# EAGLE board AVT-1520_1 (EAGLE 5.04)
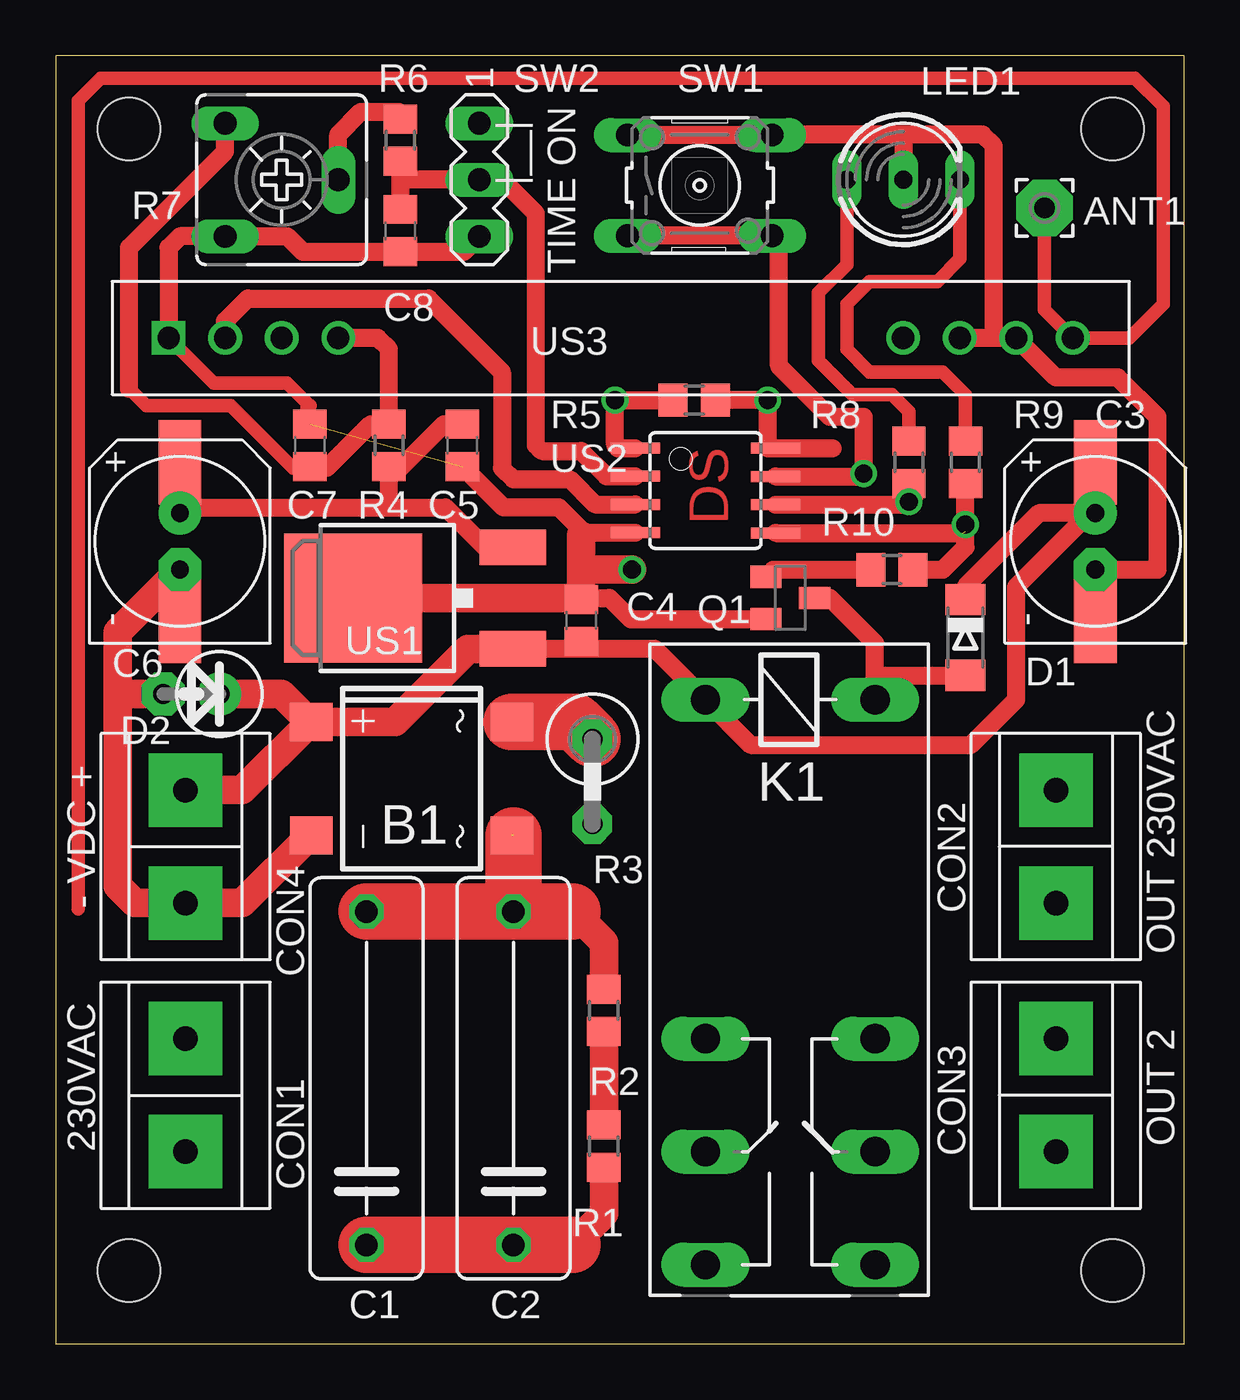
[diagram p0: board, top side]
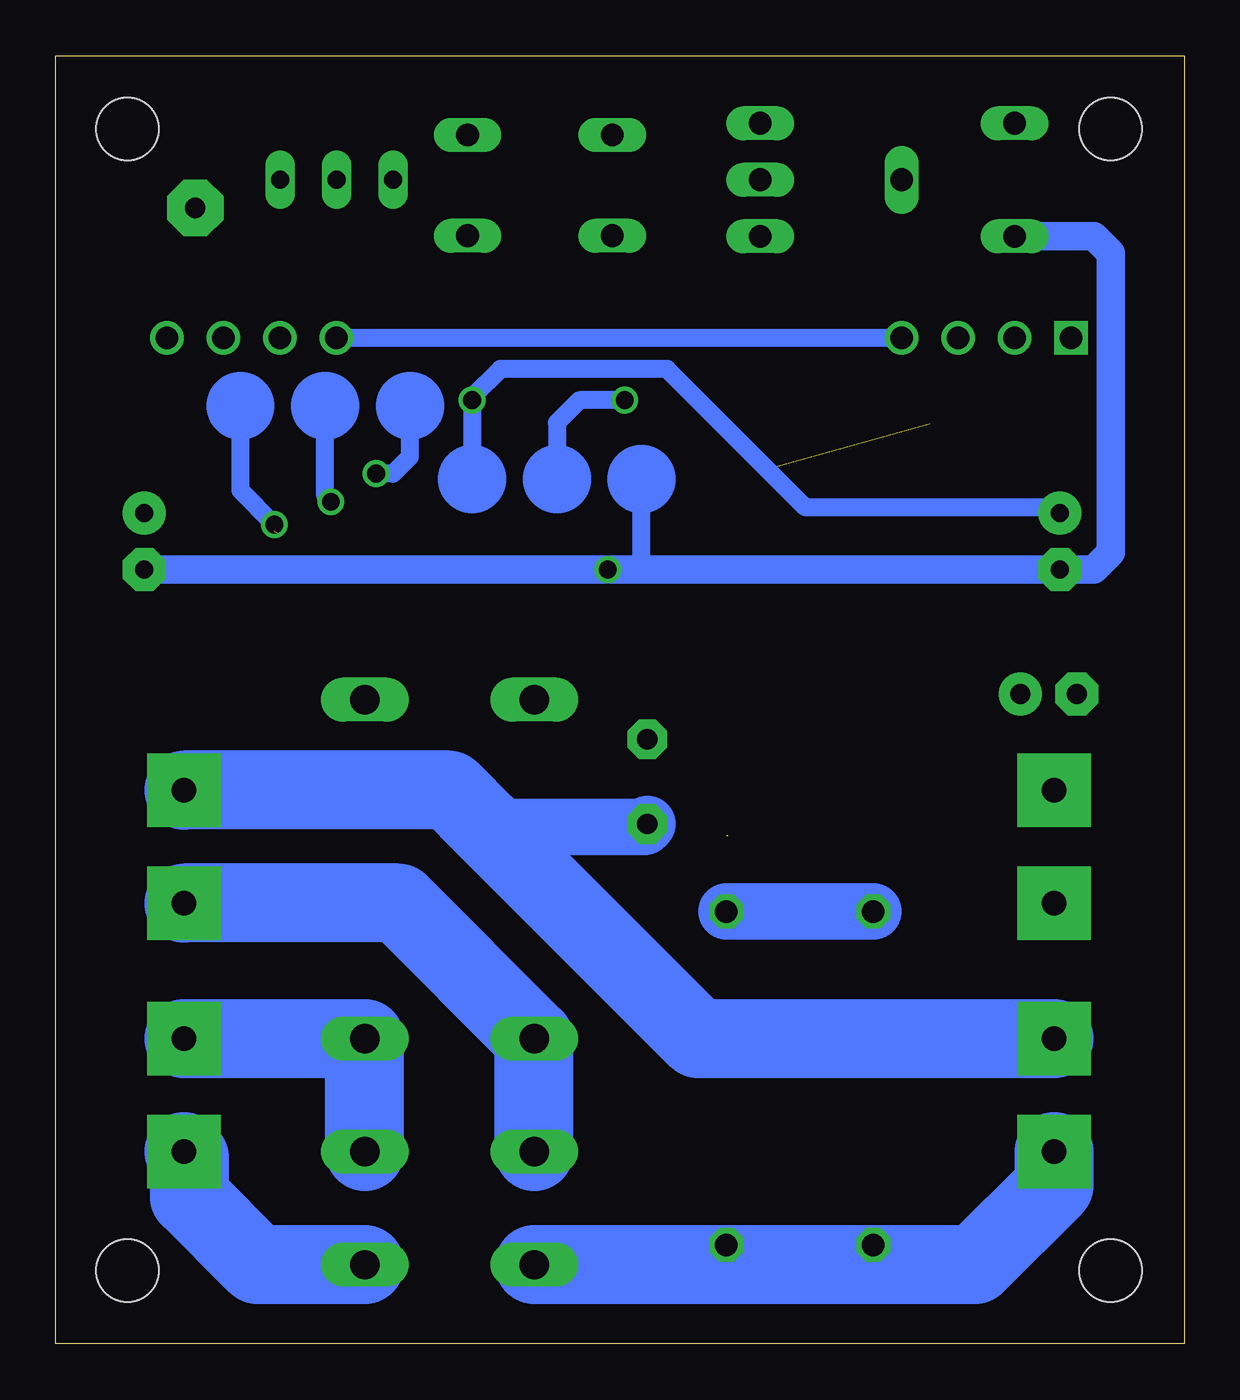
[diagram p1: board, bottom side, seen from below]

Size 50.72 x 57.9 mm. Coordinates in mm from the lower left corner, seen from the top.
Outline: 0,0 50.72,0 50.72,57.9 0,57.9 0,0
Copper layers (1*16): Top 0.035mm / dielectric 1.5mm / Bottom 0.035mm
Design rules "default": minimum track width 10mil, minimum drill 24mil, track to track 8mil, track to pad 8mil, pad to pad 8mil, via to via 8mil, smd to smd 8mil, copper to edge 40mil, drill to drill 8mil, minimum pad ring 10mil, minimum via ring 8mil, stop-mask expansion 4mil, vias tented up to drill 0mil, thermal gap 10mil
Holes 2.8 mm at 3.3,3.3 47.5,3.3 47.5,54.61 3.3,54.61

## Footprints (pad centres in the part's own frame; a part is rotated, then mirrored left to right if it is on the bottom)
2,54/0,9 = drill 0.914 pad 2.54 octagon: 1 0,0
DBS = smd 1.7 x 1.9: + -2.55,-4.5; - 2.55,-4.5; AC1 -2.55,4.5; AC2 2.55,4.5
C150-054X183 = drill 1.016 octagon: 1 -7.493,0; 2 7.493,0
MULTI_CAP = drill 0.8 pad 1.93 round: 1 1.27,0 | drill 0.8 pad 1.93 octagon: 2 -1.27,0 | smd 3.81 x 1.93: P$1 -3.556,0; P$2 3.556,0
C0805 = smd 1.3 x 1.5: 1 -0.95,0; 2 0.95,0
ARK500/2 = drill 1.1 pad 3.302 square: 1 -2.54,0; 2 2.54,0
MINIMELF = smd 1.4 x 1.8: A 1.7,0; C -1.7,0
RAD2,5 = drill 0.9 pad 1.93 octagon: A 1.27,0 | drill 0.9 pad 1.93 round: C -1.27,0
RP420 = drill 1.321 long: 11 16.51,-3.81; 12 11.43,-3.81; 14 21.59,-3.81; 21 16.51,3.81; 22 11.43,3.81; 24 21.59,3.81; A1 -3.81,-3.81; A2 -3.81,3.81
DUOLED-C-5MM = drill 0.813 long: AR 2.54,0; AX -2.54,0; C 0,0
SOT23-BEC = smd 1 x 1.4: B -0.95,-1.1; C 0,1.1; E 0.95,-1.1
R0805 = smd 1.3 x 1.5: 1 -0.95,0; 2 0.95,0
0411V = drill 0.914 pad 1.778 octagon: 1 -2.54,0; 2 1.27,0
CA6V = drill 1.016 long: A -2.54,-2.54; E 2.54,-2.54; S 0,2.54
B3F-10XX = drill 1.016 long: 1 -3.251,2.261; 2 3.251,2.261; 3 -3.251,-2.261; 4 3.251,-2.261
MA03-1 = drill 1.016 long: 1 -2.54,0; 2 0,0; 3 2.54,0
DPACK = smd 1.6 x 3: 1 -2.28,-4.8; 3 2.28,-4.8 | smd 5.8 x 6.2: 4 0,2.38
SOIC8 = smd 0.5 x 2.2: 1 -1.905,-3.154; 2 -0.645,-3.154; 3 0.625,-3.154; 4 1.895,-3.154; 5 1.905,3.154; 6 0.635,3.154; 7 -0.635,3.154; 8 -1.905,3.154
RX433 = drill 1 square: 1 -20.32,0 | drill 1 round: 2 -17.78,0; 3 -15.24,0; 4 -12.7,0; 5 12.7,0; 6 15.24,0; 7 17.78,0; 8 20.32,0

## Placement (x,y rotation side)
ANT1  [2,54/0,9]  44.45,51.05 0 top
B1  DBS101G  [DBS]  16,25.4 270 top
C1  470nF/400V  [C150-054X183]  13.97,11.94 90 top
C2  2 x 470nF/400V  [C150-054X183]  20.57,11.94 90 top
C3  220uF  [MULTI_CAP]  46.74,36.07 90 top
C4  100nF  [C0805]  23.62,32.51 90 top
C5  100nF  [C0805]  18.29,40.39 270 top
C6  220uF  [MULTI_CAP]  5.59,36.07 90 top
C7  100nF  [C0805]  11.43,40.39 90 top
C8  100nF  [C0805]  15.49,50.04 270 top
CON1  ARK500/2  [ARK500/2]  5.84,11.18 90 top
CON2  ARK500/2  [ARK500/2]  44.96,22.35 270 top
CON3  ARK500/2  [ARK500/2]  44.96,11.18 270 top
CON4  ARK500/2  [ARK500/2]  5.84,22.35 90 top
D1  1N4148  [MINIMELF]  40.89,31.75 270 top
D2  15V  [RAD2,5]  6.1,29.21 180 top
K1  RP420005  [RP420]  33.02,25.15 270 top
LED1  [DUOLED-C-5MM]  38.1,52.32 0 top
Q1  BC849  [SOT23-BEC]  33.02,33.53 270 top
R1  470k  [R0805]  24.64,8.89 90 top
R2  470k  [R0805]  24.64,14.99 90 top
R3  100R  [0411V]  24.13,24.64 270 top
R4  10R  [R0805]  14.99,40.39 90 top
R5  10k  [R0805]  28.7,42.42 0 top
R6  10k  [CA6V]  10.16,52.32 270 top
R7  1k  [R0805]  15.49,54.1 90 top
R8  1k  [R0805]  38.35,39.62 90 top
R9  1k  [R0805]  40.89,39.62 90 top
R10  10k  [R0805]  37.59,34.8 180 top
SW1  [B3F-10XX]  28.96,52.07 0 top
SW2  [MA03-1]  19.05,52.32 270 top
US1  78M05  [DPACK]  15.75,33.53 90 top
US2  TINY13  [SOIC8]  29.21,38.35 270 top
US3  RX433  [RX433]  25.4,45.21 0 top

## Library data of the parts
ANT1 = wirepad
B1 = rectifier
C1 C2 C4 C5 C7 C8 R1-R5 R7-R10 = rcl
C3 C6 CON1-CON4 = DS
D1 D2 = diode
K1 = relay
LED1 = led
Q1 = transistor-npn
R6 = pot
SW1 = switch-omron
SW2 = con-lstb
US1 = v-reg
US2 = avr-4
US3 = cmos

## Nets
+5V: C5.1 C6.1 R4.1 R5.2 US1.3 US2.8
GND: B1.- C3.2 C4.2 C5.2 C6.2 C7.2 C8.2 CON4.1 D2.A LED1.C Q1.E R6.E SW1.1 SW1.2 SW2.3 US1.4 US2.4 US3.1 US3.6 US3.7
N$1: B1.AC2 C1.2 C2.2 R2.2
N$4: B1.AC1 R3.1
N$6: CON1.2 CON2.1 R3.2
N$7: R1.2 R2.1
N$9: CON3.2 K1.24
N$10: B1.+ C3.1 C4.1 CON4.2 D1.C D2.C K1.A1 US1.1
N$11: CON2.2 K1.11
N$13: LED1.AR R9.2
N$14: LED1.AX R8.2
N$15: R8.1 US2.6
N$16: ANT1.1 US3.8
N$17: US2.3 US3.2
N$18: SW1.3 SW1.4 US2.7
N$20: Q1.B R10.2
N$21: D1.A K1.A2 Q1.C
N$22: R9.1 R10.1 US2.5
N$23: C8.1 R7.1 SW2.2 US2.2
N$24: R5.1 US2.1
N$26: R6.S R7.2
N$27: CON3.1 K1.21
N$28: C7.1 R4.2 R6.A US3.4 US3.5
N$29: C1.1 C2.1 CON1.1 K1.14 R1.1

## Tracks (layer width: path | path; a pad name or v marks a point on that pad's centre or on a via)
+5V  (via drill 0.8 pad 1.02)
  Top 0.813: US1.3 19.31,35.81 17.53,37.59 14.73,37.59 | 5.84,37.59 14.73,37.59 | 14.73,37.59 14.99,37.85 R4.1 15.05,39.37 15.49,39.37 17.46,41.34 C5.1 | 34.92,40.26 US2.8 32,40.26 v32,42.42 R5.2
  Top 1.27: C6.1 5.84,37.59
  Bottom 0.813: 32,38.86 v32,42.42 32,42.55 30.73,43.81 23.24,43.81 17.02,37.59 5.84,37.59 C6.1
GND  (via drill 0.8 pad 1.02)  (1 unrouted)
  Top 0.61: 11.3,42.29 10.41,43.18 7.11,43.18 US3.1 | 11.3,42.29 11.43,42.16 | C7.2 11.3,41.46 11.3,42.29
  Top 0.813: 23.76,36.46 US2.4 | US3.1 5.08,49.28 5.59,49.78 R6.E 10.41,49.78 11.11,49.09 C8.2 18.35,49.09 SW2.3 | SW1.1 SW1.2 32.23,54.36 38.1,54.36 | 38.1,54.36 LED1.C | 42.16,45.21 US3.6 | 42.16,45.21 42.16,53.85 41.66,54.36 38.1,54.36 | 42.16,45.21 US3.7 44.96,43.43 47.75,43.43 49.53,41.66 49.53,34.8 C3.2 | 23.76,36.46 22.63,37.59 20.13,37.59 C5.2 | 11.43,22.86 11.44,22.85 B1.- | Q1.E 25.84,32.58 24.89,33.53 23.62,33.53 | 23.62,36.32 23.76,36.46
  Top 1.27: US1.4 23.62,33.53 | 23.62,33.53 C4.2 | 2.79,29.21 2.79,20.57 3.56,19.81 CON4.1 8.38,19.81 11.43,22.86 | 2.79,29.21 2.79,32 C6.2 | 2.79,29.21 D2.A | 23.62,33.53 23.62,34.8 | 23.62,34.8 v25.91,34.8 | 23.62,34.8 23.62,36.32
  Bottom 0.813: 24.38,38.86 24.38,34.8 v25.91,34.8
  Bottom 1.27: R6.E 4.06,49.78 3.3,49.02 3.3,35.56 4.06,34.8 C6.2 C3.2
N$1  (1 unrouted)
  Top 0.813: C2.2 20.57,19.56 20.45,19.43 | R2.2 24.83,15.94 24.89,16 24.64,16.26
  Top 1.27: 23.24,19.43 24.64,18.03 24.64,16.26
  Top 2.54: C1.2 20.45,19.43 | 20.57,22.86 C2.2 23.24,19.43
  Bottom 2.54: C1.2 C2.2
N$4
  Top 2.54: R3.1 23.36,27.95 B1.AC1
N$6
  Bottom 2.54: R3.2 24.26,23.24 31.37,23.24
  Bottom 3.556: CON2.1 33.02,24.89 31.37,23.24 21.84,13.72 CON1.2
N$7
  Top 0.813: 24.57,14.04 24.38,14.22 | 24.57,14.04 R2.1 | 24.64,13.97 24.57,14.04
  Top 1.27: R1.2 24.64,13.97
N$8  (via drill 0.8 pad 1.02)
  Bottom 0.813: v36.32,39.12 35.56,39.12 34.8,39.88 34.8,42.16
N$9
  Bottom 3.556: K1.24 41.66,3.56 44.7,6.6 44.7,8.38 CON3.2
N$10
  Top 0.813: 46.48,37.34 44.2,37.34 40.89,34.04 D1.C | 23.62,31.25 US1.1 20.57,31.25 20.57,31.24 | 23.62,31.25 26.92,31.25 K1.A1 31.24,26.92 41.15,26.92 43.18,28.96 43.18,34.04 46.48,37.34 | 23.62,31.25 23.62,31.24 | 23.62,31.25 C4.1 | 11.43,27.94 11.44,27.95 B1.+ | 46.48,37.34 C3.1
  Top 1.27: US1.1 | B1.+ 15.25,27.95 18.54,31.24 20.57,31.24 | CON4.2 8.38,24.89 11.43,27.94 10.16,29.21 D2.C
N$11
  Bottom 3.556: K1.11 29.21,13.72 35.31,19.81 CON2.2
N$13
  Top 0.61: R9.2 40.89,42.67 39.88,43.69 36.58,43.69 35.56,44.7 35.56,46.74 36.58,47.75 39.62,47.75 40.64,48.77 LED1.AR
N$14
  Top 0.61: R8.2 38.35,41.91 37.59,42.67 35.81,42.67 34.29,44.2 34.29,47.24 35.56,48.51 LED1.AX
N$15  (via drill 0.8 pad 1.02)
  Top 0.813: US2.6 38.23,37.72 v38.35,37.85 38.61,38.1 38.61,38.42 R8.1
  Bottom 0.813: v38.35,37.85 38.61,38.1 38.61,42.16
N$16
  Top 0.61: 1.02,19.56 1.02,55.88 2.03,56.9 48.51,56.9 49.78,55.63 49.78,46.74 48.26,45.21 US3.8 44.45,46.48 ANT1.1
N$17
  Top 0.813: US2.3 24.25,37.73 23.11,38.86 20.57,38.86 20.07,39.37 20.07,43.69 16.76,46.99 8.64,46.99 7.62,45.97 US3.2
N$18
  Top 0.813: US2.7 36.2,38.99 36.32,39.12 36.32,41.66 34.8,41.66 32.51,43.94 32.51,49.5 SW1.4 SW1.3
N$20
  Top 0.813: Q1.B 31.94,34.48 32.26,34.8 R10.2
N$21
  Top 0.813: Q1.C 34.8,33.53 36.83,31.5 36.83,30.23 | K1.A2 36.83,30.23 | D1.A 37.01,30.05 36.83,30.23
N$22  (via drill 0.8 pad 1.02)  (1 unrouted)
  Top 0.813: v40.89,36.83 40.89,36.51 | v40.89,36.83 R9.1 | US2.5 40.77,36.45 | R10.1 39.88,34.8 40.89,35.81 v40.89,36.83
  Bottom 0.813: v40.89,36.83 42.42,38.35 42.42,42.16
N$23
  Top 0.813: US2.2 24.75,39 23.62,40.13 21.84,40.13 21.59,40.39 21.59,50.8 20.07,52.32 SW2.2 15.75,52.32 15.49,52.58 | 15.49,52.58 C8.1 | 15.49,52.58 R7.1
N$24
  Top 0.813: US2.1 25.27,40.26 25.15,40.39 25.15,42.42 R5.1
N$26
  Top 0.813: R6.S 12.7,54.36 13.72,55.37 15.43,55.37 R7.2
N$27
  Bottom 3.556: K1.21 36.83,13.72 CON3.1
N$28
  Top 0.61: 12.19,39.37 10.67,39.37 7.87,42.16 4.06,42.16 3.3,42.93
  Top 0.813: US3.4 14.48,45.21 14.99,44.7 R4.2 14.16,41.34 12.19,39.37 11.5,39.37 C7.1 | 3.3,42.93 3.3,49.28 7.62,53.59 R6.A
  Bottom 0.813: US3.4 US3.5
N$29
  Top 1.27: 23.24,4.45 24.64,5.84 R1.1
  Top 2.54: C1.1 C2.1 23.24,4.45
  Bottom 1.27: C1.1 13.84,4.32 13.84,2.92 13.21,3.56 12.57,3.56
  Bottom 3.556: K1.14 12.57,3.56 9.4,3.56 5.84,7.11 CON1.1
N$31  (via drill 0.8 pad 1.02)
  Bottom 0.813: v25.15,42.42 27.18,42.42 28.19,41.4 28.19,38.86
(copper drawn outside any net)
  shapes: Bottom area x6, Bottom circle x6

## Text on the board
Top: DS
tPlace: TIME ON | |__| | - VDC + | OUT 230VAC | 230VAC | OUT 2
